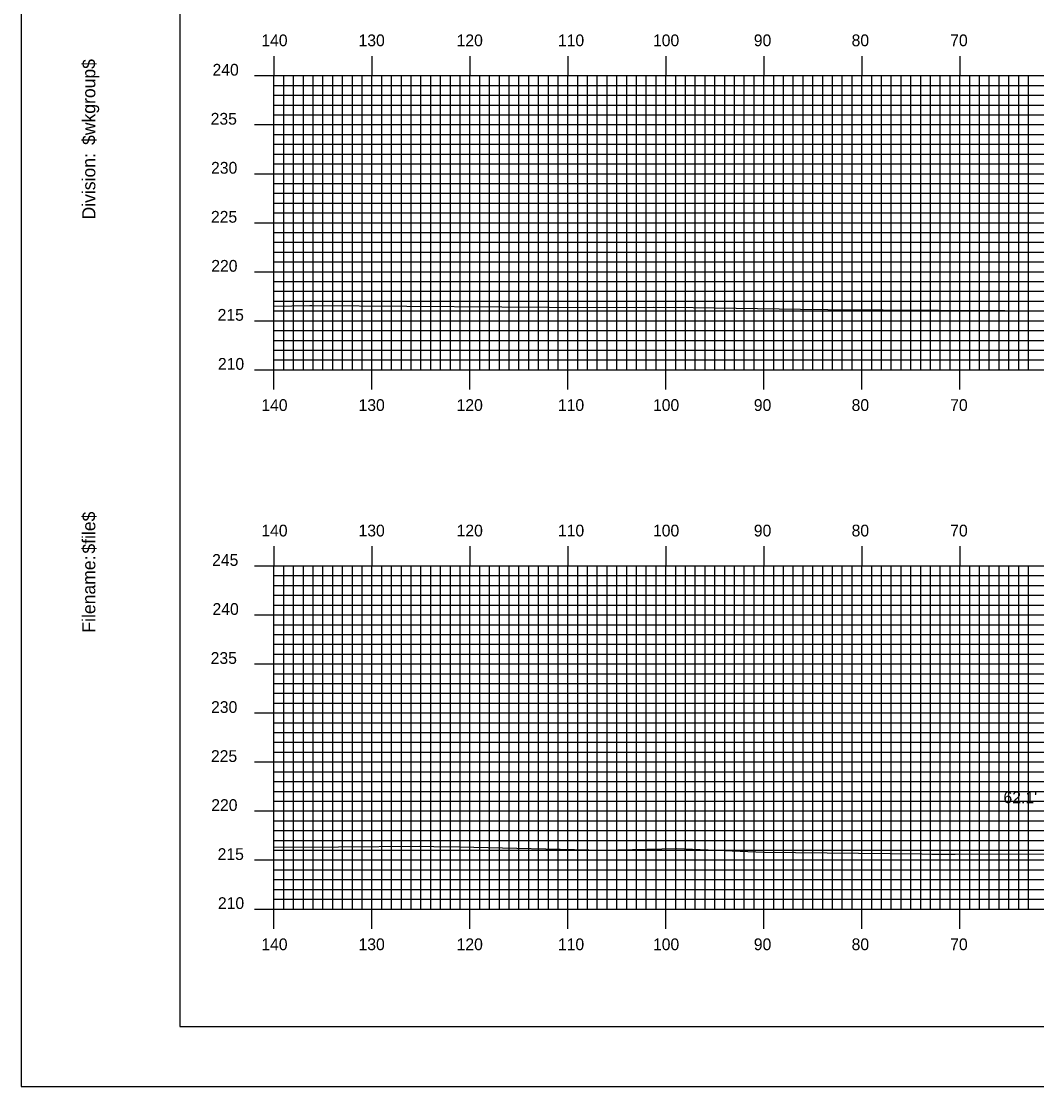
# Model space of a CAD drawing. Extents: x 1818850 to 1819194, y 442591 to 442811.
# Drawn here: x 1818850.4 to 1818954, y 442590.5 to 442699.2 of the extents above; entities that cross this region are included whole.
import ezdxf

# ---------------------------------------------------------------- set-up
doc = ezdxf.new("R2010")
doc.units = 0
for name, color, linetype in [('BORDER', 7, 'Continuous'), ('D_Text_Standard', 7, 'Continuous'), ('H_V ANNOTATION', 7, 'Continuous'), ('MAJOR', 7, 'Continuous'), ('MINOR', 7, 'Continuous'), ('PLOT BOUNDARY', 7, 'Continuous'), ('S_Roadway_Centerline', 7, 'Continuous')]:
    doc.layers.add(name, color=color, linetype=linetype)

msp = doc.modelspace()

# ---------------------------------------------------------------- linework, layer by layer
at = {"layer": 'BORDER'}
msp.add_lwpolyline([(1818866.55, 442596.67), (1819186.55, 442596.67), (1819186.55, 442806.67), (1818866.55, 442806.67)], close=True, dxfattribs=at)
at = {"layer": 'MAJOR'}
for p, q in [((1818876.15, 442695.67), (1818876.15, 442693.67)), ((1818886.15, 442695.67), (1818886.15, 442693.67)), ((1818896.15, 442695.67), (1818896.15, 442693.67)), ((1818906.15, 442695.67), (1818906.15, 442693.67)), ((1818916.15, 442695.67), (1818916.15, 442693.67)), ((1818926.15, 442695.67), (1818926.15, 442693.67)), ((1818936.15, 442695.67), (1818936.15, 442693.67)), ((1818946.15, 442695.67), (1818946.15, 442693.67)), ((1818874.15, 442693.67), (1818876.15, 442693.67)), ((1818876.15, 442693.67), (1819156.15, 442693.67)), ((1818876.15, 442663.67), (1818876.15, 442693.67)), ((1818876.15, 442663.67), (1818876.15, 442693.67)), ((1818876.15, 442693.67), (1819156.15, 442693.67)), ((1818886.15, 442663.67), (1818886.15, 442693.67)), ((1818896.15, 442663.67), (1818896.15, 442693.67)), ((1818906.15, 442663.67), (1818906.15, 442693.67)), ((1818916.15, 442663.67), (1818916.15, 442693.67)), ((1818926.15, 442663.67), (1818926.15, 442693.67)), ((1818936.15, 442663.67), (1818936.15, 442693.67)), ((1818946.15, 442663.67), (1818946.15, 442693.67)), ((1818874.15, 442688.67), (1818876.15, 442688.67)), ((1818876.15, 442688.67), (1819156.15, 442688.67)), ((1818874.15, 442683.67), (1818876.15, 442683.67)), ((1818876.15, 442683.67), (1819156.15, 442683.67)), ((1818874.15, 442678.67), (1818876.15, 442678.67)), ((1818876.15, 442678.67), (1819156.15, 442678.67)), ((1818874.15, 442673.67), (1818876.15, 442673.67)), ((1818876.15, 442673.67), (1819156.15, 442673.67)), ((1818874.15, 442668.67), (1818876.15, 442668.67)), ((1818876.15, 442668.67), (1819156.15, 442668.67)), ((1818874.15, 442663.67), (1818876.15, 442663.67)), ((1818876.15, 442663.67), (1819156.15, 442663.67)), ((1818876.15, 442663.67), (1819156.15, 442663.67)), ((1818876.15, 442661.66), (1818876.15, 442663.67)), ((1818886.15, 442661.66), (1818886.15, 442663.67)), ((1818896.15, 442661.66), (1818896.15, 442663.67)), ((1818906.15, 442661.66), (1818906.15, 442663.67)), ((1818916.15, 442661.66), (1818916.15, 442663.67)), ((1818926.15, 442661.66), (1818926.15, 442663.67)), ((1818936.15, 442661.66), (1818936.15, 442663.67)), ((1818946.15, 442661.66), (1818946.15, 442663.67)), ((1818876.15, 442645.67), (1818876.15, 442643.67)), ((1818886.15, 442645.67), (1818886.15, 442643.67)), ((1818896.15, 442645.67), (1818896.15, 442643.67)), ((1818906.15, 442645.67), (1818906.15, 442643.67)), ((1818916.15, 442645.67), (1818916.15, 442643.67)), ((1818926.15, 442645.67), (1818926.15, 442643.67)), ((1818936.15, 442645.67), (1818936.15, 442643.67)), ((1818946.15, 442645.67), (1818946.15, 442643.67)), ((1818874.15, 442643.67), (1818876.15, 442643.67)), ((1818876.15, 442643.67), (1819156.15, 442643.67)), ((1818876.15, 442608.67), (1818876.15, 442643.67)), ((1818876.15, 442608.67), (1818876.15, 442643.67)), ((1818876.15, 442643.67), (1819156.15, 442643.67)), ((1818886.15, 442608.67), (1818886.15, 442643.67)), ((1818896.15, 442608.67), (1818896.15, 442643.67)), ((1818906.15, 442608.67), (1818906.15, 442643.67)), ((1818916.15, 442608.67), (1818916.15, 442643.67)), ((1818926.15, 442608.67), (1818926.15, 442643.67)), ((1818936.15, 442608.67), (1818936.15, 442643.67)), ((1818946.15, 442608.67), (1818946.15, 442643.67)), ((1818874.15, 442638.67), (1818876.15, 442638.67)), ((1818876.15, 442638.67), (1819156.15, 442638.67)), ((1818874.15, 442633.67), (1818876.15, 442633.67)), ((1818876.15, 442633.67), (1819156.15, 442633.67)), ((1818874.15, 442628.67), (1818876.15, 442628.67)), ((1818876.15, 442628.67), (1819156.15, 442628.67)), ((1818874.15, 442623.67), (1818876.15, 442623.67)), ((1818876.15, 442623.67), (1819156.15, 442623.67)), ((1818874.15, 442618.67), (1818876.15, 442618.67)), ((1818876.15, 442618.67), (1819156.15, 442618.67)), ((1818874.15, 442613.67), (1818876.15, 442613.67)), ((1818876.15, 442613.67), (1819156.15, 442613.67)), ((1818874.15, 442608.67), (1818876.15, 442608.67)), ((1818876.15, 442608.67), (1819156.15, 442608.67)), ((1818876.15, 442608.67), (1819156.15, 442608.67)), ((1818876.15, 442606.66), (1818876.15, 442608.67)), ((1818886.15, 442606.66), (1818886.15, 442608.67)), ((1818896.15, 442606.66), (1818896.15, 442608.67)), ((1818906.15, 442606.66), (1818906.15, 442608.67)), ((1818916.15, 442606.66), (1818916.15, 442608.67)), ((1818926.15, 442606.66), (1818926.15, 442608.67)), ((1818936.15, 442606.66), (1818936.15, 442608.67)), ((1818946.15, 442606.66), (1818946.15, 442608.67))]:
    msp.add_line(p, q, dxfattribs=at)
at = {"layer": 'MINOR'}
for p, q in [((1818877.15, 442663.67), (1818877.15, 442693.67)), ((1818878.15, 442663.67), (1818878.15, 442693.67)), ((1818879.15, 442663.67), (1818879.15, 442693.67)), ((1818880.15, 442663.67), (1818880.15, 442693.67)), ((1818881.15, 442663.67), (1818881.15, 442693.67)), ((1818882.15, 442663.67), (1818882.15, 442693.67)), ((1818883.15, 442663.67), (1818883.15, 442693.67)), ((1818884.15, 442663.67), (1818884.15, 442693.67)), ((1818885.15, 442663.67), (1818885.15, 442693.67)), ((1818887.15, 442663.67), (1818887.15, 442693.67)), ((1818888.15, 442663.67), (1818888.15, 442693.67)), ((1818889.15, 442663.67), (1818889.15, 442693.67)), ((1818890.15, 442663.67), (1818890.15, 442693.67)), ((1818891.15, 442663.67), (1818891.15, 442693.67)), ((1818892.15, 442663.67), (1818892.15, 442693.67)), ((1818893.15, 442663.67), (1818893.15, 442693.67)), ((1818894.15, 442663.67), (1818894.15, 442693.67)), ((1818895.15, 442663.67), (1818895.15, 442693.67)), ((1818897.15, 442663.67), (1818897.15, 442693.67)), ((1818898.15, 442663.67), (1818898.15, 442693.67)), ((1818899.15, 442663.67), (1818899.15, 442693.67)), ((1818900.15, 442663.67), (1818900.15, 442693.67)), ((1818901.15, 442663.67), (1818901.15, 442693.67)), ((1818902.15, 442663.67), (1818902.15, 442693.67)), ((1818903.15, 442663.67), (1818903.15, 442693.67)), ((1818904.15, 442663.67), (1818904.15, 442693.67)), ((1818905.15, 442663.67), (1818905.15, 442693.67)), ((1818907.15, 442663.67), (1818907.15, 442693.67)), ((1818908.15, 442663.67), (1818908.15, 442693.67)), ((1818909.15, 442663.67), (1818909.15, 442693.67)), ((1818910.15, 442663.67), (1818910.15, 442693.67)), ((1818911.15, 442663.67), (1818911.15, 442693.67)), ((1818912.15, 442663.67), (1818912.15, 442693.67)), ((1818913.15, 442663.67), (1818913.15, 442693.67)), ((1818914.15, 442663.67), (1818914.15, 442693.67)), ((1818915.15, 442663.67), (1818915.15, 442693.67)), ((1818917.15, 442663.67), (1818917.15, 442693.67)), ((1818918.15, 442663.67), (1818918.15, 442693.67)), ((1818919.15, 442663.67), (1818919.15, 442693.67)), ((1818920.15, 442663.67), (1818920.15, 442693.67)), ((1818921.15, 442663.67), (1818921.15, 442693.67)), ((1818922.15, 442663.67), (1818922.15, 442693.67)), ((1818923.15, 442663.67), (1818923.15, 442693.67)), ((1818924.15, 442663.67), (1818924.15, 442693.67)), ((1818925.15, 442663.67), (1818925.15, 442693.67)), ((1818927.15, 442663.67), (1818927.15, 442693.67)), ((1818928.15, 442663.67), (1818928.15, 442693.67)), ((1818929.15, 442663.67), (1818929.15, 442693.67)), ((1818930.15, 442663.67), (1818930.15, 442693.67)), ((1818931.15, 442663.67), (1818931.15, 442693.67)), ((1818932.15, 442663.67), (1818932.15, 442693.67)), ((1818933.15, 442663.67), (1818933.15, 442693.67)), ((1818934.15, 442663.67), (1818934.15, 442693.67)), ((1818935.15, 442663.67), (1818935.15, 442693.67)), ((1818937.15, 442663.67), (1818937.15, 442693.67)), ((1818938.15, 442663.67), (1818938.15, 442693.67)), ((1818939.15, 442663.67), (1818939.15, 442693.67)), ((1818940.15, 442663.67), (1818940.15, 442693.67)), ((1818941.15, 442663.67), (1818941.15, 442693.67)), ((1818942.15, 442663.67), (1818942.15, 442693.67)), ((1818943.15, 442663.67), (1818943.15, 442693.67)), ((1818944.15, 442663.67), (1818944.15, 442693.67)), ((1818945.15, 442663.67), (1818945.15, 442693.67)), ((1818947.15, 442663.67), (1818947.15, 442693.67)), ((1818948.15, 442663.67), (1818948.15, 442693.67)), ((1818949.15, 442663.67), (1818949.15, 442693.67)), ((1818950.15, 442663.67), (1818950.15, 442693.67)), ((1818951.15, 442663.67), (1818951.15, 442693.67)), ((1818952.15, 442663.67), (1818952.15, 442693.67)), ((1818953.15, 442663.67), (1818953.15, 442693.67)), ((1818876.15, 442692.67), (1819156.15, 442692.67)), ((1818876.15, 442692.67), (1818878.16, 442692.67)), ((1818876.15, 442691.67), (1819156.15, 442691.67)), ((1818876.15, 442691.67), (1818878.16, 442691.67)), ((1818876.15, 442690.67), (1819156.15, 442690.67)), ((1818876.15, 442690.67), (1818878.16, 442690.67)), ((1818876.15, 442689.67), (1819156.15, 442689.67)), ((1818876.15, 442689.67), (1818878.16, 442689.67)), ((1818876.15, 442687.67), (1819156.15, 442687.67)), ((1818876.15, 442687.67), (1818878.16, 442687.67)), ((1818876.15, 442686.67), (1819156.15, 442686.67)), ((1818876.15, 442686.67), (1818878.16, 442686.67)), ((1818876.15, 442685.67), (1819156.15, 442685.67)), ((1818876.15, 442685.67), (1818878.16, 442685.67)), ((1818876.15, 442684.67), (1819156.15, 442684.67)), ((1818876.15, 442684.67), (1818878.16, 442684.67)), ((1818876.15, 442682.67), (1819156.15, 442682.67)), ((1818876.15, 442682.67), (1818878.16, 442682.67)), ((1818876.15, 442681.67), (1819156.15, 442681.67)), ((1818876.15, 442681.67), (1818878.16, 442681.67)), ((1818876.15, 442680.67), (1819156.15, 442680.67)), ((1818876.15, 442680.67), (1818878.16, 442680.67)), ((1818876.15, 442679.67), (1819156.15, 442679.67)), ((1818876.15, 442679.67), (1818878.16, 442679.67)), ((1818876.15, 442677.67), (1819156.15, 442677.67)), ((1818876.15, 442677.67), (1818878.16, 442677.67)), ((1818876.15, 442676.67), (1819156.15, 442676.67)), ((1818876.15, 442676.67), (1818878.16, 442676.67)), ((1818876.15, 442675.67), (1819156.15, 442675.67)), ((1818876.15, 442675.67), (1818878.16, 442675.67)), ((1818876.15, 442674.67), (1819156.15, 442674.67)), ((1818876.15, 442674.67), (1818878.16, 442674.67)), ((1818876.15, 442672.67), (1819156.15, 442672.67)), ((1818876.15, 442672.67), (1818878.16, 442672.67)), ((1818876.15, 442671.67), (1819156.15, 442671.67)), ((1818876.15, 442671.67), (1818878.16, 442671.67)), ((1818876.15, 442670.67), (1819156.15, 442670.67)), ((1818876.15, 442670.67), (1818878.16, 442670.67)), ((1818876.15, 442669.67), (1819156.15, 442669.67)), ((1818876.15, 442669.67), (1818878.16, 442669.67)), ((1818876.15, 442667.67), (1819156.15, 442667.67)), ((1818876.15, 442667.67), (1818878.16, 442667.67)), ((1818876.15, 442666.67), (1819156.15, 442666.67)), ((1818876.15, 442666.67), (1818878.16, 442666.67)), ((1818876.15, 442665.67), (1819156.15, 442665.67)), ((1818876.15, 442665.67), (1818878.16, 442665.67)), ((1818876.15, 442664.67), (1819156.15, 442664.67)), ((1818876.15, 442664.67), (1818878.16, 442664.67)), ((1818877.15, 442608.67), (1818877.15, 442643.67)), ((1818878.15, 442608.67), (1818878.15, 442643.67)), ((1818879.15, 442608.67), (1818879.15, 442643.67)), ((1818880.15, 442608.67), (1818880.15, 442643.67)), ((1818881.15, 442608.67), (1818881.15, 442643.67)), ((1818882.15, 442608.67), (1818882.15, 442643.67)), ((1818883.15, 442608.67), (1818883.15, 442643.67)), ((1818884.15, 442608.67), (1818884.15, 442643.67)), ((1818885.15, 442608.67), (1818885.15, 442643.67)), ((1818887.15, 442608.67), (1818887.15, 442643.67)), ((1818888.15, 442608.67), (1818888.15, 442643.67)), ((1818889.15, 442608.67), (1818889.15, 442643.67)), ((1818890.15, 442608.67), (1818890.15, 442643.67)), ((1818891.15, 442608.67), (1818891.15, 442643.67)), ((1818892.15, 442608.67), (1818892.15, 442643.67)), ((1818893.15, 442608.67), (1818893.15, 442643.67)), ((1818894.15, 442608.67), (1818894.15, 442643.67)), ((1818895.15, 442608.67), (1818895.15, 442643.67)), ((1818897.15, 442608.67), (1818897.15, 442643.67)), ((1818898.15, 442608.67), (1818898.15, 442643.67)), ((1818899.15, 442608.67), (1818899.15, 442643.67)), ((1818900.15, 442608.67), (1818900.15, 442643.67)), ((1818901.15, 442608.67), (1818901.15, 442643.67)), ((1818902.15, 442608.67), (1818902.15, 442643.67)), ((1818903.15, 442608.67), (1818903.15, 442643.67)), ((1818904.15, 442608.67), (1818904.15, 442643.67)), ((1818905.15, 442608.67), (1818905.15, 442643.67)), ((1818907.15, 442608.67), (1818907.15, 442643.67)), ((1818908.15, 442608.67), (1818908.15, 442643.67)), ((1818909.15, 442608.67), (1818909.15, 442643.67)), ((1818910.15, 442608.67), (1818910.15, 442643.67)), ((1818911.15, 442608.67), (1818911.15, 442643.67)), ((1818912.15, 442608.67), (1818912.15, 442643.67)), ((1818913.15, 442608.67), (1818913.15, 442643.67)), ((1818914.15, 442608.67), (1818914.15, 442643.67)), ((1818915.15, 442608.67), (1818915.15, 442643.67)), ((1818917.15, 442608.67), (1818917.15, 442643.67)), ((1818918.15, 442608.67), (1818918.15, 442643.67)), ((1818919.15, 442608.67), (1818919.15, 442643.67)), ((1818920.15, 442608.67), (1818920.15, 442643.67)), ((1818921.15, 442608.67), (1818921.15, 442643.67)), ((1818922.15, 442608.67), (1818922.15, 442643.67)), ((1818923.15, 442608.67), (1818923.15, 442643.67)), ((1818924.15, 442608.67), (1818924.15, 442643.67)), ((1818925.15, 442608.67), (1818925.15, 442643.67)), ((1818927.15, 442608.67), (1818927.15, 442643.67)), ((1818928.15, 442608.67), (1818928.15, 442643.67)), ((1818929.15, 442608.67), (1818929.15, 442643.67)), ((1818930.15, 442608.67), (1818930.15, 442643.67)), ((1818931.15, 442608.67), (1818931.15, 442643.67)), ((1818932.15, 442608.67), (1818932.15, 442643.67)), ((1818933.15, 442608.67), (1818933.15, 442643.67)), ((1818934.15, 442608.67), (1818934.15, 442643.67)), ((1818935.15, 442608.67), (1818935.15, 442643.67)), ((1818937.15, 442608.67), (1818937.15, 442643.67)), ((1818938.15, 442608.67), (1818938.15, 442643.67)), ((1818939.15, 442608.67), (1818939.15, 442643.67)), ((1818940.15, 442608.67), (1818940.15, 442643.67)), ((1818941.15, 442608.67), (1818941.15, 442643.67)), ((1818942.15, 442608.67), (1818942.15, 442643.67)), ((1818943.15, 442608.67), (1818943.15, 442643.67)), ((1818944.15, 442608.67), (1818944.15, 442643.67)), ((1818945.15, 442608.67), (1818945.15, 442643.67)), ((1818947.15, 442608.67), (1818947.15, 442643.67)), ((1818948.15, 442608.67), (1818948.15, 442643.67)), ((1818949.15, 442608.67), (1818949.15, 442643.67)), ((1818950.15, 442608.67), (1818950.15, 442643.67)), ((1818951.15, 442608.67), (1818951.15, 442643.67)), ((1818952.15, 442608.67), (1818952.15, 442643.67)), ((1818953.15, 442608.67), (1818953.15, 442643.67)), ((1818876.15, 442642.67), (1819156.15, 442642.67)), ((1818876.15, 442642.67), (1818878.16, 442642.67)), ((1818876.15, 442641.67), (1819156.15, 442641.67)), ((1818876.15, 442641.67), (1818878.16, 442641.67)), ((1818876.15, 442640.67), (1819156.15, 442640.67)), ((1818876.15, 442640.67), (1818878.16, 442640.67)), ((1818876.15, 442639.67), (1819156.15, 442639.67)), ((1818876.15, 442639.67), (1818878.16, 442639.67)), ((1818876.15, 442637.67), (1819156.15, 442637.67)), ((1818876.15, 442637.67), (1818878.16, 442637.67)), ((1818876.15, 442636.67), (1819156.15, 442636.67)), ((1818876.15, 442636.67), (1818878.16, 442636.67)), ((1818876.15, 442635.67), (1819156.15, 442635.67)), ((1818876.15, 442635.67), (1818878.16, 442635.67)), ((1818876.15, 442634.67), (1819156.15, 442634.67)), ((1818876.15, 442634.67), (1818878.16, 442634.67)), ((1818876.15, 442632.67), (1819156.15, 442632.67)), ((1818876.15, 442632.67), (1818878.16, 442632.67)), ((1818876.15, 442631.67), (1819156.15, 442631.67)), ((1818876.15, 442631.67), (1818878.16, 442631.67)), ((1818876.15, 442630.67), (1819156.15, 442630.67)), ((1818876.15, 442630.67), (1818878.16, 442630.67)), ((1818876.15, 442629.67), (1819156.15, 442629.67)), ((1818876.15, 442629.67), (1818878.16, 442629.67)), ((1818876.15, 442627.67), (1819156.15, 442627.67)), ((1818876.15, 442627.67), (1818878.16, 442627.67)), ((1818876.15, 442626.67), (1819156.15, 442626.67)), ((1818876.15, 442626.67), (1818878.16, 442626.67)), ((1818876.15, 442625.67), (1819156.15, 442625.67)), ((1818876.15, 442625.67), (1818878.16, 442625.67)), ((1818876.15, 442624.67), (1819156.15, 442624.67)), ((1818876.15, 442624.67), (1818878.16, 442624.67)), ((1818876.15, 442622.67), (1819156.15, 442622.67)), ((1818876.15, 442622.67), (1818878.16, 442622.67)), ((1818876.15, 442621.67), (1819156.15, 442621.67)), ((1818876.15, 442621.67), (1818878.16, 442621.67)), ((1818876.15, 442620.67), (1819156.15, 442620.67)), ((1818876.15, 442620.67), (1818878.16, 442620.67)), ((1818876.15, 442619.67), (1819156.15, 442619.67)), ((1818876.15, 442619.67), (1818878.16, 442619.67)), ((1818876.15, 442617.67), (1819156.15, 442617.67)), ((1818876.15, 442617.67), (1818878.16, 442617.67)), ((1818876.15, 442616.67), (1819156.15, 442616.67)), ((1818876.15, 442616.67), (1818878.16, 442616.67)), ((1818876.15, 442615.67), (1819156.15, 442615.67)), ((1818876.15, 442615.67), (1818878.16, 442615.67)), ((1818876.15, 442614.67), (1819156.15, 442614.67)), ((1818876.15, 442614.67), (1818878.16, 442614.67)), ((1818876.15, 442612.67), (1819156.15, 442612.67)), ((1818876.15, 442612.67), (1818878.16, 442612.67)), ((1818876.15, 442611.67), (1819156.15, 442611.67)), ((1818876.15, 442611.67), (1818878.16, 442611.67)), ((1818876.15, 442610.67), (1819156.15, 442610.67)), ((1818876.15, 442610.67), (1818878.16, 442610.67)), ((1818876.15, 442609.67), (1819156.15, 442609.67)), ((1818876.15, 442609.67), (1818878.16, 442609.67))]:
    msp.add_line(p, q, dxfattribs=at)
at = {"layer": 'PLOT BOUNDARY'}
msp.add_lwpolyline([(1818850.36, 442590.55), (1819190.36, 442590.55), (1819190.36, 442810.55), (1818850.36, 442810.55)], close=True, dxfattribs=at)
at = {"layer": 'S_Roadway_Centerline'}
for points in [[(1818876.15, 442670.16), (1818879.81, 442670.23), (1818880.03, 442670.23), (1818909.11, 442670.03), (1818914.93, 442670.06), (1818918.93, 442670.01), (1818929.9, 442669.84), (1818932.68, 442669.8), (1818943.95, 442669.74), (1818957.52, 442669.67), (1818963.63, 442669.73), (1818972.89, 442669.72), (1818980.88, 442669.33), (1818987.41, 442669.1), (1818998.09, 442669.77), (1819006.66, 442670.52), (1819026.49, 442671.35), (1819039.87, 442672.8), (1819045.19, 442673.38), (1819064.86, 442675.27), (1819066.46, 442675.46), (1819066.98, 442675.51), (1819070.78, 442675.98), (1819083.88, 442677.52)], [(1818876.15, 442614.98), (1818882.74, 442615.01), (1818891, 442615.09), (1818892.47, 442615.04), (1818895.07, 442615.02), (1818909.74, 442614.66), (1818917.24, 442614.85), (1818926.15, 442614.47), (1818942.28, 442614.3), (1818943.28, 442614.27), (1818943.83, 442614.28), (1818945.66, 442614.26), (1818966.04, 442614.3)]]:
    msp.add_lwpolyline(points, dxfattribs=at)

# ---------------------------------------------------------------- texts
at = {"layer": 'BORDER'}
for s, p in [('$wkgroup$', (1818857.92, 442686.6)), ('Division:', (1818857.92, 442679)), ('$file$', (1818857.92, 442644.92)), ('Filename:', (1818857.92, 442636.86))]:
    msp.add_text(s, height=1.339, rotation=90, dxfattribs=at).set_placement(p)
at = {"layer": 'D_Text_Standard'}
msp.add_text("62.1'", height=1.2, dxfattribs=at).set_placement((1818950.6, 442619.46))
at = {"layer": 'H_V ANNOTATION'}
for s, p in [('140', (1818874.86, 442696.67)), ('130', (1818884.78, 442696.67)), ('120', (1818894.79, 442696.67)), ('110', (1818905.13, 442696.67)), ('100', (1818914.83, 442696.67)), ('90', (1818925.12, 442696.67)), ('80', (1818935.1, 442696.67)), ('70', (1818945.16, 442696.67)), ('240', (1818869.88, 442693.67)), ('235', (1818869.69, 442688.67)), ('230', (1818869.73, 442683.67)), ('225', (1818869.72, 442678.67)), ('220', (1818869.75, 442673.67)), ('215', (1818870.4, 442668.67)), ('210', (1818870.43, 442663.67)), ('140', (1818874.86, 442659.47)), ('130', (1818884.78, 442659.47)), ('120', (1818894.79, 442659.47)), ('110', (1818905.13, 442659.47)), ('100', (1818914.83, 442659.47)), ('90', (1818925.12, 442659.47)), ('80', (1818935.1, 442659.47)), ('70', (1818945.16, 442659.47)), ('140', (1818874.86, 442646.67)), ('130', (1818884.78, 442646.67)), ('120', (1818894.79, 442646.67)), ('110', (1818905.13, 442646.67)), ('100', (1818914.83, 442646.67)), ('90', (1818925.12, 442646.67)), ('80', (1818935.1, 442646.67)), ('70', (1818945.16, 442646.67)), ('245', (1818869.84, 442643.67)), ('240', (1818869.88, 442638.67)), ('235', (1818869.69, 442633.67)), ('230', (1818869.73, 442628.67)), ('225', (1818869.72, 442623.67)), ('220', (1818869.75, 442618.67)), ('215', (1818870.4, 442613.67)), ('210', (1818870.43, 442608.67)), ('140', (1818874.86, 442604.47)), ('130', (1818884.78, 442604.47)), ('120', (1818894.79, 442604.47)), ('110', (1818905.13, 442604.47)), ('100', (1818914.83, 442604.47)), ('90', (1818925.12, 442604.47)), ('80', (1818935.1, 442604.47)), ('70', (1818945.16, 442604.47))]:
    msp.add_text(s, height=1.2, dxfattribs=at).set_placement(p)
at = {"layer": 'MAJOR'}
for p in [(1818876.14, 442663.67), (1818876.14, 442608.67)]:
    msp.add_text('-', height=0.012, dxfattribs=at).set_placement(p)

doc.saveas('drawing.dxf')
